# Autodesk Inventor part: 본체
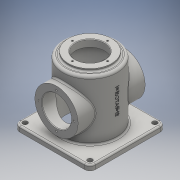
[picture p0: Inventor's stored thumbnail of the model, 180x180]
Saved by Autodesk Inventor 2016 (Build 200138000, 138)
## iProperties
Created: 2019-08
Part Number: 본체
Material: 일반
Document SubType Name: Modeling
Designer: user
Density: 1 g/cm^3
Appearance: 기본값
Mass: 414.921 g
Surface Area: 1160.06 cm^2
Volume: 414.921 cm^3
Author: user
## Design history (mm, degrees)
sketch "스케치1"
  geometry: L1 (70, -70)-(-70, -70); L2 (-70, -70)-(-70, 70); L3 (-70, 70)-(70, 70); L4 (70, 70)-(70, -70); L5 (70, -70)-(-70, 70); L6 (-70, -70)-(70, 70); 1 further point
  constraints: 12 end point, 2 midpoint, 2 parallel, 1 horizontal, 1 perpendicular
  dimensions: "d0" = 140 distance of L2.end L3.end; "d1" = 140 distance of L1.end L2.end
extrude "돌출1" new body sketch "스케치1" distance "d2" = 10; taper "d3" = 0 deg
fillet "모깎기1" dims "d4" = 10
hole "구멍1" diameter "d7" = 9; stored, may be unused: countersink angle "d11" = 90 deg, drill point angle "d13" = 118 deg; dims "d5" = 10, "d6" = 10, "d8" = 6, "d9" = 4, "d10" = 2, "d12" = 8
hole "구멍2" diameter "d16" = 9; stored, may be unused: countersink angle "d20" = 90 deg, drill point angle "d22" = 118 deg; dims "d14" = 10, "d15" = 10, "d17" = 6, "d18" = 4, "d19" = 2, "d21" = 8
hole "구멍3" diameter "d25" = 9; stored, may be unused: countersink angle "d29" = 90 deg, drill point angle "d31" = 118 deg; dims "d23" = 10, "d24" = 10, "d26" = 6, "d27" = 4, "d28" = 2, "d30" = 8
hole "구멍4" diameter "d34" = 9; stored, may be unused: countersink angle "d38" = 90 deg, drill point angle "d40" = 118 deg; dims "d32" = 10, "d33" = 10, "d35" = 6, "d36" = 4, "d37" = 2, "d39" = 8
sketch "스케치2"
  geometry: C1 r 50 at (0, 0); 1 further point
  constraints: 1 centre point, 1 coincident
  dimensions: "d41" = 100 diameter of C1
extrude "돌출2" join sketch "스케치2" distance "d42" = 110; taper "d43" = 0 deg
sketch "스케치3"
  geometry: C1 r 40 at (0, 0); 1 further point
  constraints: 1 centre point, 1 coincident
  dimensions: "d44" = 80 diameter of C1
extrude "돌출3" join sketch "스케치3" distance "d45" = 5; taper "d46" = 0 deg
sketch "스케치4"
  geometry: L1 (-50, 10)-(-50, 120) reference; L2 (-50, 120)-(-40, 120) reference; L3 (-40, 120)-(-40, 125) reference; L4 (-40, 125)-(40, 125) reference; L5 (40, 125)-(40, 120) reference; L6 (40, 120)-(50, 120) reference; L7 (50, 120)-(50, 10) reference; L8 (50, 10)-(70, 10) reference; L9 (70, 10)-(70, 0) reference; L10 (70, 0)-(-70, 0) reference; L11 (-70, 0)-(-70, 10) reference; L12 (-70, 10)-(-50, 10) reference; C1 r 40 at (0, 60); 2 further points
  constraints: 1 centre point, 1 coincident, 1 tangent
  dimensions: "d47" = 60 distance from line of L10 point (0, 60); "d48" = 80 diameter of C1
extrude "돌출4" join sketch "스케치4" stored distance "d49" = 124; taper "d50" = 0 deg
hole "구멍5" diameter "d53" = 54; stored, may be unused: countersink angle "d57" = 90 deg, drill point angle "d59" = 118 deg; dims "d51" = 10, "d52" = 10, "d54" = 6, "d55" = 4, "d56" = 2, "d58" = 8
hole "구멍6" diameter "d62" = 54; stored, may be unused: countersink angle "d66" = 90 deg, drill point angle "d68" = 118 deg; dims "d60" = 10, "d61" = 10, "d63" = 6, "d64" = 4, "d65" = 2, "d67" = 8
sketch "스케치5"
  geometry: C1 r 45 at (0, 0); 1 further point
  constraints: 1 centre point, 1 coincident
  dimensions: "d69" = 90 diameter of C1
extrude "돌출5" cut sketch "스케치5" distance "d70" = 112; taper "d71" = 0 deg
sketch "스케치6"
  geometry: C1 r 27 at (0, 0) reference; C2 r 40 at (0, 0) reference; 2 further points
  constraints: 1 vertical alignment
  dimensions: "d72" = 32.5 distance of point (0, 0) point (0, 32.5)
hole "구멍7" sketch "스케치6" at (0, 32.5) diameter "d73" = 3.242; stored, may be unused: countersink angle "d77" = 90 deg, drill point angle "d79" = 118 deg; dims "d74" = 8, "d75" = 4, "d76" = 2, "d78" = 10
sketch "스케치7"
  geometry: L1 (-55.969, -60)-(-55.969, -50) reference; L2 (-55.969, -50)-(55.969, -50) reference; L3 (55.969, -50)-(55.969, -60) reference; L4 (55.969, -60)-(-55.969, -60) reference; L5 (-64.031, -50)-(-64.031, -60) reference; L6 (-64.031, -60)-(-69.798, -60) reference; L7 (-69.798, -60)-(-69.798, -50) reference; L8 (-69.798, -50)-(-64.031, -50) reference; L9 (69.798, -50)-(69.798, -60) reference; L10 (69.798, -60)-(64.031, -60) reference; L11 (64.031, -60)-(64.031, -50) reference; L12 (64.031, -50)-(69.798, -50) reference; C1 r 27 at (0, 0) reference; C2 r 40 at (0, 0) reference; 2 further points
  constraints: 1 vertical alignment
  dimensions: "d83" = 32.5 distance of C1.centre point (0, 32.5)
hole "구멍8" sketch "스케치7" at (0, 32.5) diameter "d84" = 3.242; stored, may be unused: countersink angle "d88" = 90 deg, drill point angle "d90" = 118 deg; dims "d85" = 8, "d86" = 4, "d87" = 2, "d89" = 10
fillet "모깎기3" dims "d95" = 3
chamfer "모따기1" distance "d96" = 1; stored, may be unused: second distance "d97" = 2, angle "d98" = 45 deg
node "작업 평면3"
sketch "스케치10" dims "d0" = 140, "d1" = 140, "d23" = 10, "d24" = 10
  geometry: L1 (-60, 0)-(60, 0) reference; 3 further points
  constraints: 1 midpoint, 1 vertical alignment, 1 other
  dimensions: "d108" = 70 distance from line of L1 point (0, 70)
feature "엠보싱3" sketch "스케치10" dims "d0" = 140, "d1" = 140, "d109" = 0.5, "d110" = 0
fillet "모깎기4" dims "d111" = 5
fillet "모깎기5" dims "d112" = 3
fillet "모깎기6" dims "d113" = 3
node "솔리드1"
pattern_circular "원형 패턴1" dims angle "d81" = 360 deg
pattern_circular "원형 패턴2" dims angle "d92" = 360 deg
mirror "대칭1"
node "절단 모서리 투영1"
node "절단 모서리 투영2"
node "절단 모서리 투영3"
